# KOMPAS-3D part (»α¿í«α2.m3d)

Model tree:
1. Эскиз:1
2. Операция выдавливания:1
     Расстояние 1 = 16
3. Эскиз:2
4. Операция выдавливания:2
     Расстояние 1 = 16; Расстояние 2 = 16
5. Эскиз:5
6. Вырезать элемент выдавливания:1
     Расстояние 2 = 10.15; Расстояние 1 = 10.15
7. Ломаная:1
8. Скругление кривых:3
9. Скругление
10. Усеченная кривая ( 1 )
11. Усеченная кривая ( 2 )
     Радиус = 7.56869
12. Перпендикулярная плоскость:2
13. Эскиз:7
14. Кинематическая операция:1
     Толщина стенки 1 = 1; Толщина стенки 2 = 1
15. Эскиз:8
16. Операция выдавливания:6
     Расстояние 1 = 16; Расстояние 2 = 5
17. Эскиз:9
18. Операция выдавливания:7
     Расстояние 1 = 16; Расстояние 2 = 5
19. Эскиз:11
20. Операция выдавливания:8
     Расстояние 1 = 2; Расстояние 2 = 5
21. Эскиз:12
22. Вырезать элемент выдавливания:3
     Расстояние 1 = 0.3
23. Эскиз:13
24. Вырезать элемент выдавливания:4
     Расстояние 1 = 0.3
25. Эскиз:14
26. Вырезать элемент выдавливания:5
     Расстояние 1 = 0.3
27. Эскиз:15
28. Вырезать элемент выдавливания:6
     Расстояние 1 = 1
29. Эскиз:16
30. Вырезать элемент выдавливания:7
     Расстояние 1 = 0.3
31. Эскиз:17
32. Вырезать элемент выдавливания:8
     Расстояние 1 = 0.3
33. Эскиз:18
34. Вырезать элемент выдавливания:9
     Расстояние 1 = 2
35. Эскиз:19
36. Операция выдавливания:9
     Расстояние 1 = 0.2
37. Эскиз:20
38. Вырезать элемент выдавливания:10
     Расстояние 1 = 1
39. Эскиз:21
40. Операция выдавливания:10
     Расстояние 1 = 0.1

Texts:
  прибор2
  Сплав АЛ8  ГОСТ 1583-93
